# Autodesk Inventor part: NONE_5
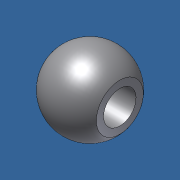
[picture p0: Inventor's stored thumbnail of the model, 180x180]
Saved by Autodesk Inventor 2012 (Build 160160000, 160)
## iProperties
Created: 2013-10
Part Number: NONE_5
Material: Default
Document SubType Name: Modeling
Designer: Admin
Density: 1 g/cm^3
Author: Admin
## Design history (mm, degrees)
node "Sankq_7011P566_Handle1"
node "Base1"
body "Solid1"
